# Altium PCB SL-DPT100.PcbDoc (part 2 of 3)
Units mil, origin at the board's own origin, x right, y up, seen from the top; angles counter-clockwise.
Board outline 2881.89 x 2169.29 mil, 4 copper layers (Top Layer, VCC, GND, Bottom Layer); 176 components, 168 nets, 589 pads, 369 vias.
Unrouted connection lines stored in the file: 2.
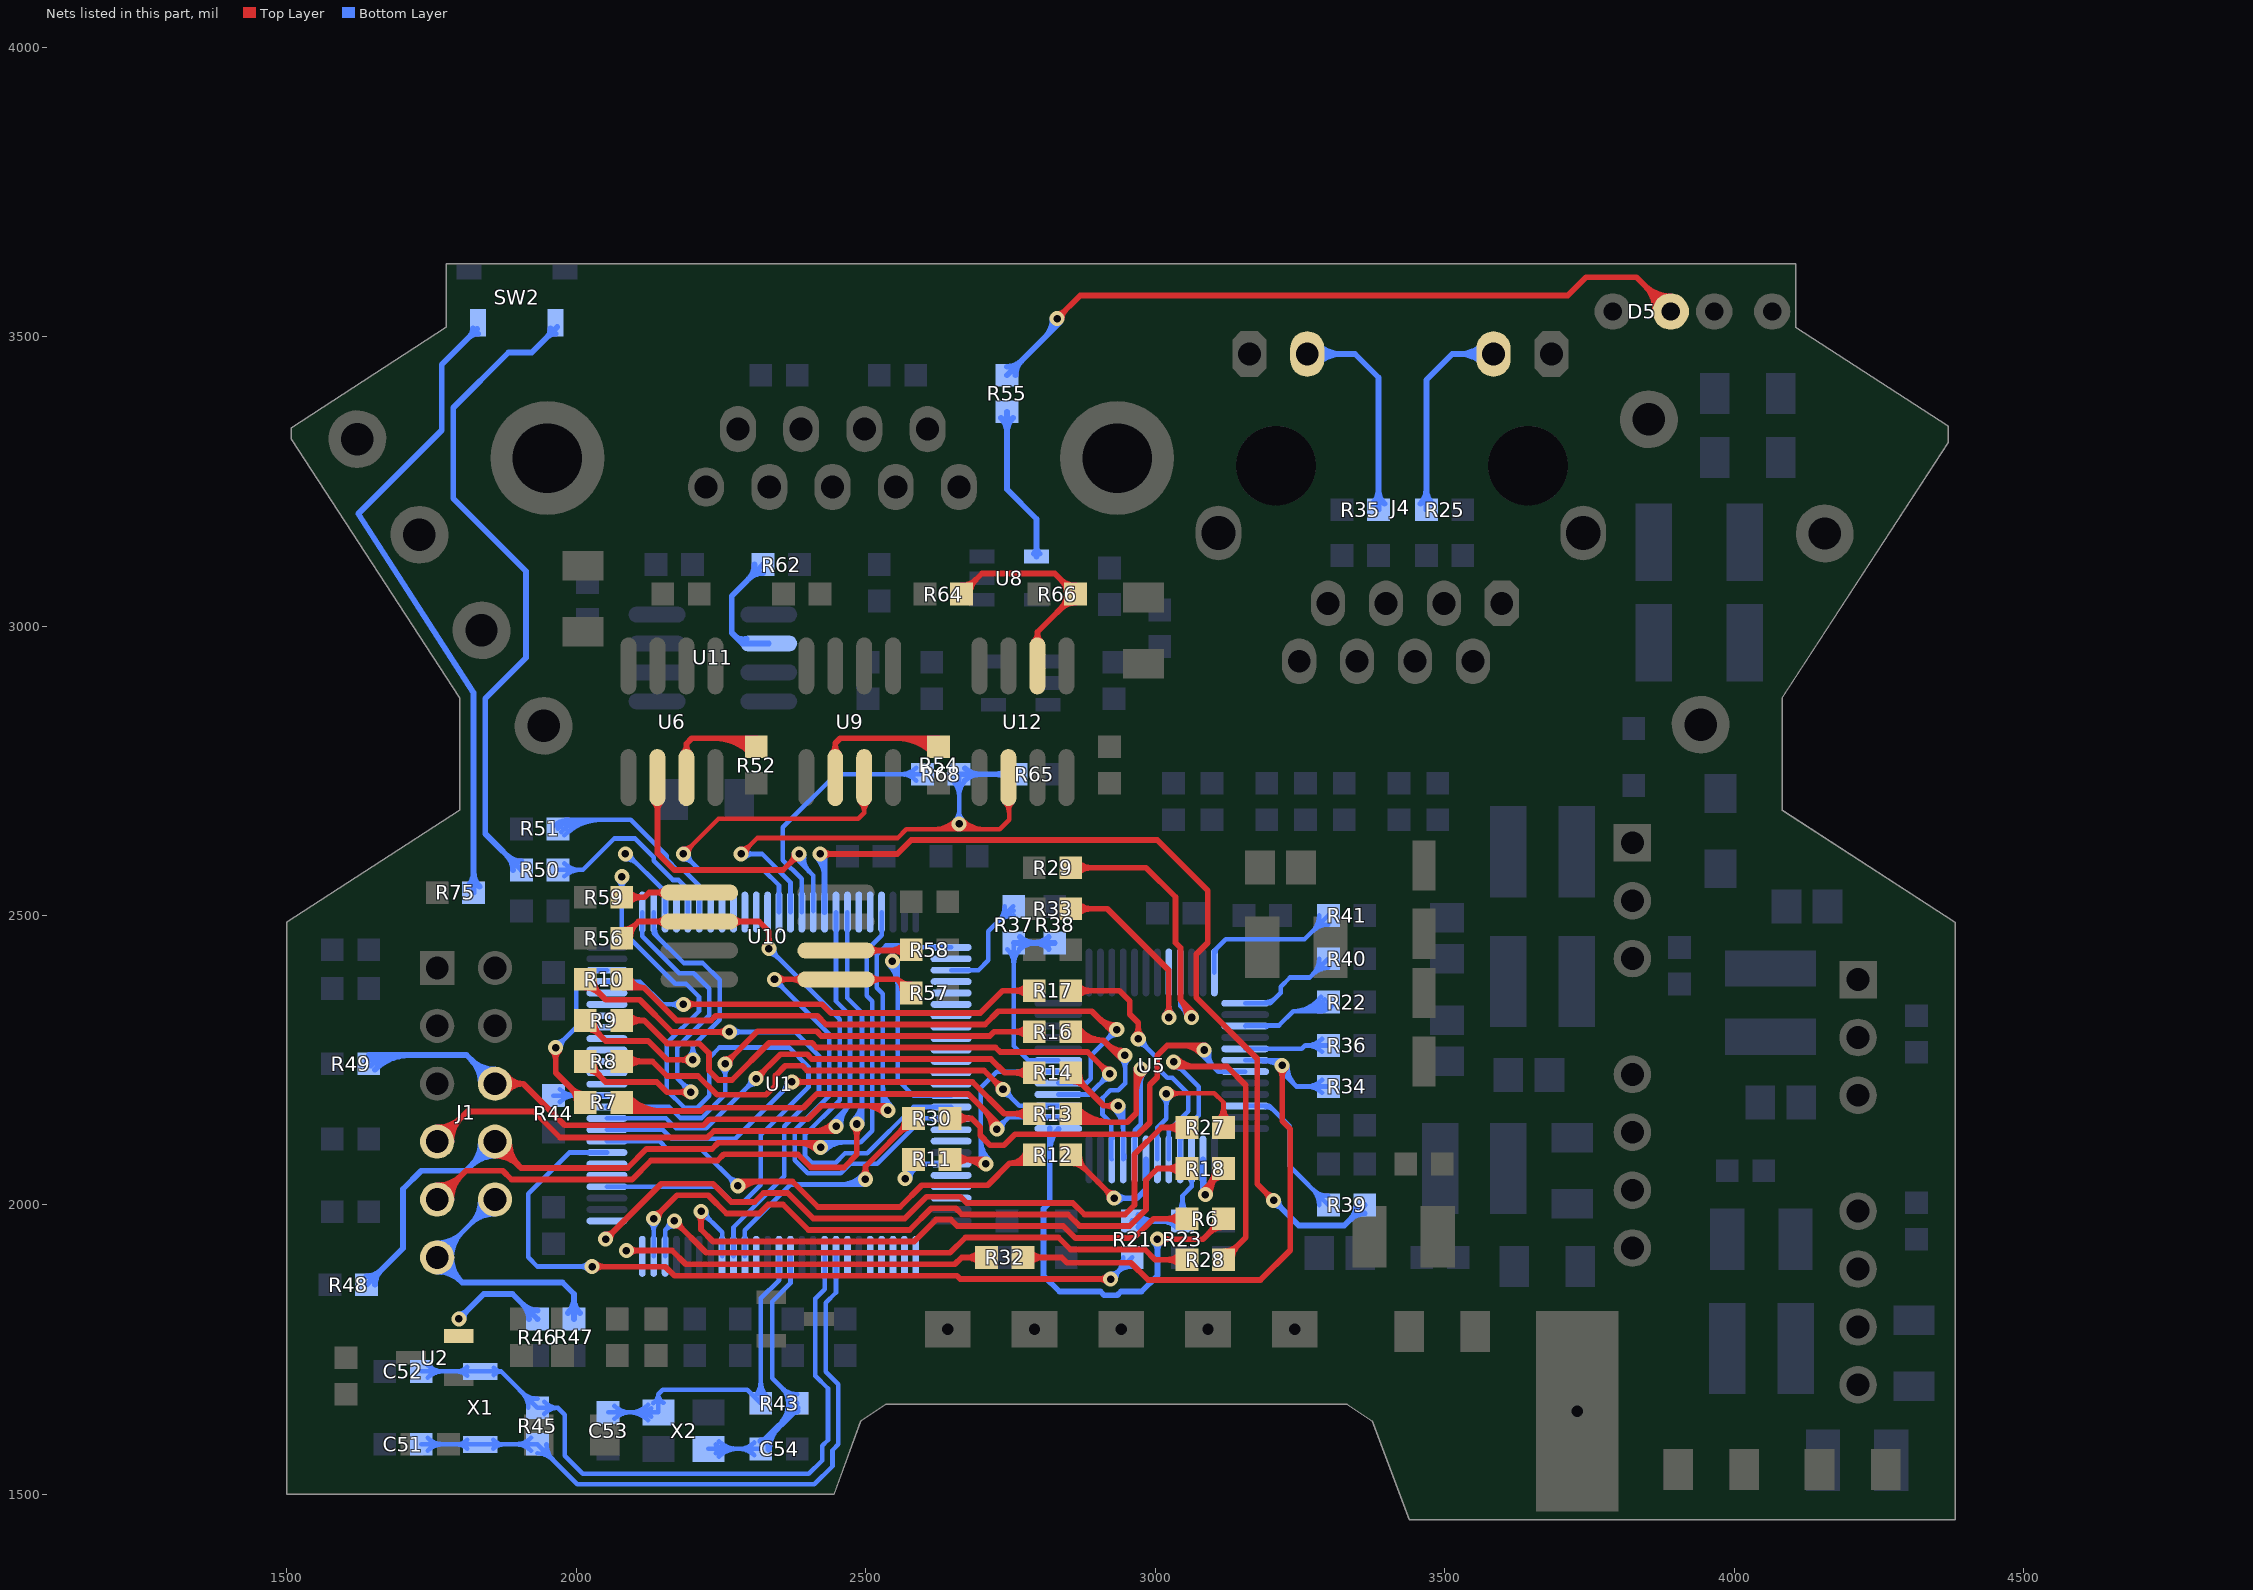
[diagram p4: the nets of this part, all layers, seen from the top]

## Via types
v1: diameter 26, hole 13, Top Layer to Bottom Layer, tented both sides, 363 vias
v2: diameter 26, hole 13, Top Layer to Bottom Layer, 4 vias
v3: diameter 27.56, hole 27.56, Top Layer to Bottom Layer, tented both sides, 2 vias

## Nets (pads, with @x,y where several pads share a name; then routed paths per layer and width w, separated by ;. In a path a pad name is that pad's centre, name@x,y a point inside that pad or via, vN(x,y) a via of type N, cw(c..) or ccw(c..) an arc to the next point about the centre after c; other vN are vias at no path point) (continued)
NetD5_2: D5.2 R55.2 | length 1547.6
  Top Layer w10: v1(2830.71,3531.02) 2870.55,3570.87 3712.6,3570.87 3744.09,3602.36 3831.5,3602.36 D5.2@3890.55,3543.31 ; v1@2830.71,3539.02 ccw(c2830.71,3558.34) 2844.37,3544.68 ccw(c2858.02,3531.02) v1@2838.71,3531.02 ; D5.2@3864.06,3543.31 ccw(c3800.09,3543.31) 3845.32,3588.54 ccw(c3890.55,3633.77) D5.2@3890.55,3569.8 ; D5.2@3874.06,3543.31 ccw(c3834.23,3543.31) 3862.39,3571.47 ccw(c3890.55,3599.63) D5.2@3890.55,3559.8
  Bottom Layer w10: R55.2@2744.09,3433.07 v1@2836.26,3525.24 ; R55.2@2744.09,3447.76 ccw(c2744.09,3483.21) 2769.16,3458.14 ccw(c2794.23,3433.07) R55.2@2758.78,3433.07 ; 2809.03,3498.01 ccw(c2776.02,3531.02) v1@2822.71,3531.02 ; 2826.11,3515.08 ccw(c2810.16,3531.02) v1@2832.71,3531.02
NetJ1_10: J1.10 J1.11 R47.1 | length 975.2
  Bottom Layer w8: J1.11@1759.84,1909.45 J1.10@1858.27,2007.87 ; J1.11@1759.84,1926.98 ccw(c1759.84,1969.29) 1789.76,1939.37 ccw(c1819.69,1909.45) J1.11@1777.37,1909.45 ; J1.11@1759.84,1934.98 ccw(c1759.84,1996.61) 1803.42,1953.03 ccw(c1847,1909.45) J1.11@1785.37,1909.45 ; J1.10@1834.32,2009.45 cw(c1772.69,2009.45) 1816.26,1965.87 cw(c1859.84,1922.29) J1.10@1859.84,1983.92 ; J1.10@1842.32,2009.45 cw(c1800,2009.45) 1829.92,1979.53 cw(c1859.84,1949.61) J1.10@1859.84,1991.92
  Bottom Layer w10: J1.11@1759.84,1884.92 cw(c1759.84,1825.71) 1801.71,1867.58 cw(c1843.58,1909.45) J1.11@1784.37,1909.45 ; J1.11@1759.84,1894.92 cw(c1759.84,1859.85) 1784.64,1884.65 cw(c1809.44,1909.45) J1.11@1774.37,1909.45 ; J1.11@1759.84,1909.45 1803.15,1866.14 1976.38,1866.14 1996.06,1846.46 R47.1@1996.06,1803.15 ; R47.1@1985.68,1813.53 ccw(c1960.61,1838.6) 1996.06,1838.6 ccw(c2031.52,1838.6) R47.1@2006.45,1813.53
NetJ4_10: J4.10 R25.1 | length 562.7
  Bottom Layer w10: R25.1@3458.12,3211.17 ccw(c3433.05,3236.24) 3468.5,3236.24 ccw(c3503.96,3236.24) R25.1@3478.89,3211.17 ; R25.1@3468.5,3200.79 3468.5,3425.2 3513.19,3469.88 J4.10@3584.46,3469.88 ; J4.10@3567.11,3452.53 ccw(c3525.24,3410.66) 3525.24,3469.88 ccw(c3525.24,3529.09) J4.10@3567.11,3487.22 ; J4.10@3574.19,3459.61 ccw(c3549.39,3434.81) 3549.39,3469.88 ccw(c3549.39,3504.95) J4.10@3574.19,3480.15
NetJ4_11: J4.11 R35.1 | length 572
  Bottom Layer w10: J4.11@3262.81,3469.88 3345.08,3469.88 3385.83,3429.13 R35.1@3385.83,3200.79 ; J4.11@3273.08,3459.61 cw(c3297.88,3434.81) 3297.88,3469.88 cw(c3297.88,3504.95) J4.11@3273.08,3480.15 ; J4.11@3280.15,3452.53 cw(c3322.02,3410.66) 3322.02,3469.88 cw(c3322.02,3529.09) J4.11@3280.15,3487.22 ; R35.1@3375.44,3211.17 ccw(c3350.37,3236.24) 3385.83,3236.24 ccw(c3421.28,3236.24) R35.1@3396.21,3211.17
NetR6_1: R6.1 U5.1 | length 833.5
  Top Layer w10: v1(3003.94,1940.94) 3082.68,1940.94 R6.1@3118.11,1976.38 ; v1@3009.59,1935.29 cw(c3023.25,1921.63) 3023.25,1940.94 cw(c3023.25,1960.26) v1@3009.59,1946.6 ; R6.1@3103.43,1976.38 cw(c3067.97,1976.38) 3093.04,1951.31 cw(c3118.11,1926.24) R6.1@3118.11,1961.69
  Bottom Layer w10: 2817.91,2094.06 cw(c2870.51,2094.06) U5.1@2833.32,2131.25 ; U5.1@2817.91,2132.63 2817.91,2004.26 2807.09,1993.43 2807.09,1877.95 2834.65,1850.39 2905.51,1850.39 2911.7,1844.2 2934.76,1844.2 2940.95,1850.39 2976.38,1850.39 3003.94,1877.95 v1(3003.94,1940.94) ; v1@2998.28,1935.29 cw(c2984.62,1921.63) 3003.94,1921.63 cw(c3023.25,1921.63) v1@3009.59,1935.29
NetR7_1: R7.1 U5.2 | length 1038.9
  Top Layer w10: R7.1@2074.98,2173.41 ccw(c2102.03,2200.45) 2102.03,2162.2 ; R7.1@2079.13,2162.6 2079.53,2162.2 2216.14,2162.2 2222.07,2168.13 2392.04,2168.13 2415.84,2191.93 2676.89,2191.93 v1@2732.36,2136.46 ; R7.1@2082.05,2180.48 ccw(c2126.17,2224.59) 2126.17,2162.2 ; R7.1@2089.12,2187.55 ccw(c2150.31,2248.74) 2150.31,2162.2 ; 2704.87,2163.95 cw(c2671.92,2131.01) v1@2718.51,2131.01 ; 2721.94,2146.88 cw(c2706.06,2131.01) v1@2728.51,2131.01
  Bottom Layer w8: v1@2726.38,2130.91 2747.32,2151.85 U5.2@2832.52,2151.85 ; v1@2726.51,2140.01 ccw(c2726.51,2161.67) 2741.83,2146.35 ; v1@2735.51,2131.01 cw(c2757.31,2131.01) 2741.9,2146.42
  other v1: 2726.51,2131.01
NetR8_1: R8.1 U5.3 | length 957.6
  Top Layer w10: R8.1@2078.74,2248.03 2131.64,2248.03 2156.84,2222.83 2210.52,2222.83 2243.08,2190.27 2328.06,2190.27 2344.09,2206.3 2344.09,2223.43 2361.11,2240.44 2390.77,2240.44 2398.8,2232.4 2704.61,2232.4 v1(2737.2,2199.8) ; R8.1@2089.12,2237.65 cw(c2114.19,2212.58) 2114.19,2248.03 cw(c2114.19,2283.48) R8.1@2089.12,2258.42 ; v1@2729.2,2199.8 ccw(c2709.89,2199.8) 2723.55,2213.46 ccw(c2737.2,2227.12) v1@2737.2,2207.8
  Bottom Layer w8: v1@2737.05,2200.08 2737.05,2199.96 2765.47,2171.54 U5.3@2832.52,2171.54 ; v1@2737.2,2190.8 cw(c2737.2,2169.08) 2752.57,2184.44 cw(c2767.93,2199.8) v1@2746.2,2199.8
NetR9_1: R9.1 U5.4 | length 1176
  Top Layer w10: R9.1@2078.74,2318.9 2117.11,2318.9 2157.07,2278.93 2212.61,2278.93 2229.24,2262.3 2229.24,2232.17 2245.55,2215.86 2269,2215.86 2333.27,2280.13 2407.2,2280.13 2415.24,2272.09 2724.48,2272.09 2732.31,2264.25 2883.39,2264.25 v1(2921.26,2226.38) ; R9.1@2089.12,2308.51 cw(c2114.19,2283.44) 2114.19,2318.9 cw(c2114.19,2354.35) R9.1@2089.12,2329.28 ; v1@2913.26,2226.38 ccw(c2893.95,2226.38) 2907.6,2240.04 ccw(c2921.26,2253.69) v1@2921.26,2234.38
  Bottom Layer w8: U5.4@2832.68,2190.94 2886.45,2190.94 v1@2922.07,2226.56 ; 2905.45,2209.94 ccw(c2889.02,2226.38) v1@2912.26,2226.38 ; 2906.97,2211.46 cw(c2921.26,2197.16) v1@2921.26,2217.38
NetR10_1: R10.1 U5.5 | length 1215.9
  Top Layer w10: R10.1@2081.61,2375.08 2117.05,2375.08 ; R10.1@2083.26,2390.98 ccw(c2104,2396.55) 2104,2375.08 ; R10.1@2092.92,2393.58 ccw(c2117.05,2400.06) 2117.05,2375.08 ; 2900.85,2324.35 ccw(c2933.66,2357.16) v1@2933.66,2310.76 ; 2917.92,2307.28 ccw(c2933.66,2323.02) v1@2933.66,2300.76 ; v1@2928.35,2296.85 2890.55,2334.65 2728.85,2334.65 2705.97,2311.77 2431.68,2311.77 2416.71,2326.74 2240.91,2326.74 2232.79,2318.61 2173.51,2318.61 2117.05,2375.08
  Bottom Layer w8: U5.5@2832.68,2210.63 2880.91,2210.63 2888.65,2218.37 2888.65,2257.54 v1@2933.86,2302.76 ; 2918.16,2287.06 ccw(c2902.46,2302.76) v1@2924.66,2302.76 ; 2918.63,2287.53 cw(c2933.66,2272.5) v1@2933.66,2293.76
  other v1: 2933.66,2302.76
NetR11_1: R11.1 U5.6 | length 516.9
  Top Layer w10: R11.1@2645.67,2078.74 v1@2708.66,2078.74 ; R11.1@2656.05,2068.36 cw(c2681.12,2043.29) 2681.12,2078.74 cw(c2681.12,2114.19) R11.1@2656.05,2089.12 ; 2669.35,2078.74 cw(c2669.35,2032.54) v1@2702.02,2065.21 ; 2693.5,2078.74 cw(c2693.5,2056.69) v1@2709.09,2072.28
  Bottom Layer w8: v1@2698.82,2069.88 2698.82,2202.76 2726.38,2230.32 U5.6@2832.68,2230.32 ; 2698.82,2094.67 ccw(c2731.48,2094.67) v1@2708.38,2071.57 ; 2698.82,2113.98 ccw(c2750.79,2113.98) v1@2714.04,2077.23
  other v1: 2707.68,2070.87
NetR12_1: R12.1 U5.43 | length 390.7
  Top Layer w10: R12.1@2854.33,2086.61 2901.29,2039.65 v1(2929.13,2011.81) ; 2915.47,2025.48 cw(c2901.81,2011.81) v1@2921.13,2011.81 ; 2915.49,2025.46 ccw(c2929.13,2039.11) v1@2929.13,2019.81 ; 2879.4,2061.55 cw(c2904.47,2086.61) 2869.02,2086.61 ccw(c2904.47,2086.61) 2879.4,2061.55 ; 2879.4,2061.55 ccw(c2854.33,2036.48) 2854.33,2071.93 cw(c2854.33,2036.48) 2879.4,2061.55
  Bottom Layer w10: v1(2929.13,2011.81) 2968.5,2011.81 2984.25,2027.56 U5.43@2984.25,2078.74 ; v1@2934.79,2006.15 cw(c2948.45,1992.5) 2948.45,2011.81 cw(c2948.45,2031.12) v1@2934.79,2017.47
NetR13_1: R13.1 U5.44 | length 594.2
  Top Layer w10: R13.1@2850.57,2153.72 ccw(c2876.95,2180.1) 2876.95,2142.79 ; R13.1@2854.34,2142.85 2854.4,2142.79 2951.89,2142.79 2967.4,2158.31 v1@2967.4,2235.94 ; R13.1@2857.64,2160.79 ccw(c2901.1,2204.25) 2901.1,2142.79 ; R13.1@2864.71,2167.86 ccw(c2925.24,2228.39) 2925.24,2142.79 ; 2967.4,2196.63 cw(c3014,2196.63) v1@2981.05,2229.58 ; 2967.4,2220.77 cw(c2989.86,2220.77) v1@2973.98,2236.65
  Bottom Layer w8: U5.44@2964.57,2078.74 2964.69,2078.87 2964.69,2129.06 2975.39,2139.76 v1@2975.39,2238.19 ; v1@2969.03,2228.87 cw(c2953.67,2213.51) 2975.39,2213.51 cw(c2997.12,2213.51) v1@2981.76,2228.87
  other v1: 2975.39,2235.24
NetR14_1: R14.1 U5.45 | length 382
  Top Layer w10: R14.1@2854.33,2213.66 cw(c2854.33,2178.21) 2879.4,2203.28 cw(c2904.47,2228.35) R14.1@2869.02,2228.35 ; R14.1@2854.33,2228.35 2911.42,2171.26 v1(2936.02,2171.26) ; v1@2930.37,2165.6 ccw(c2916.71,2151.95) 2916.71,2171.26 ccw(c2916.71,2190.57) v1@2930.37,2176.92
  Bottom Layer w8: v1@2929.66,2164.9 cw(c2892.91,2128.15) 2944.88,2128.15 ; v1@2935.32,2170.55 cw(c2912.22,2147.46) 2944.88,2147.46 ; U5.45@2944.88,2101.2 U5.45@2944.88,2078.74 ; v1@2944.88,2172.24 U5.45@2944.88,2078.74 ; U5.45@2946.79,2086.19 2946.72,2086.13 2946.72,2080.58 U5.45@2944.88,2078.74
NetR16_1: R16.1 U5.46 | length 517.3
  Top Layer w10: R16.1@2849.96,2296.19 ccw(c2872.18,2311.53) R16.1@2872.18,2284.53 ; R16.1@2858.19,2301.87 ccw(c2891.23,2324.67) 2891.23,2284.53 ; R16.1@2858.39,2284.53 2910.28,2284.53 v1@2942.36,2252.44 ; R16.1@2866.42,2307.55 ccw(c2910.27,2337.81) 2910.27,2284.53 ; 2915.93,2278.88 ccw(c2946.41,2309.36) v1@2947.61,2266.26 ; 2932.35,2262.45 ccw(c2947.3,2277.41) v1@2947.89,2256.27
  Bottom Layer w8: 2924.12,2121.38 ccw(c2932.4,2121.38) U5.46@2926.54,2115.52 ; U5.46@2925.2,2078.74 2924.12,2079.82 2924.12,2141.07 2909.18,2156.01 2909.18,2184.77 2922.51,2198.1 2936.29,2198.1 2948.1,2209.91 v1@2948.1,2258.59 ; v1@2941.47,2251.9 cw(c2925.46,2235.89) 2948.1,2235.89 ; 2948.1,2237.19 cw(c2968.92,2237.19) v1@2954.2,2251.9
  other v1: 2947.83,2258.27
NetR17_1: R17.1 U5.41 | length 563.7
  Top Layer w10: R17.1@2854.33,2370.08 2897.64,2370.08 2938.58,2370.08 2956.24,2352.43 2956.24,2329.47 2970.87,2314.84 v1@2970.87,2287.01 ; R17.1@2864.71,2359.7 cw(c2889.78,2334.63) 2889.78,2370.08 cw(c2889.78,2405.53) R17.1@2864.71,2380.46 ; v1@2965.21,2292.47 ccw(c2951.55,2306.13) 2970.87,2306.13 ccw(c2990.18,2306.13) v1@2976.52,2292.47
  Bottom Layer w8: v1@2970.87,2277.81 cw(c2970.87,2256.56) 2985.89,2271.59 ; v1@2970.87,2286.61 3002.24,2255.24 3002.24,2238.71 3021.09,2219.86 3029.91,2219.86 3057.35,2192.41 3057.35,2162.04 3023.62,2128.31 U5.41@3023.62,2078.74 ; v1@2979.87,2286.81 ccw(c3002.07,2286.81) 2986.37,2271.11
  other v1: 2970.87,2286.81
NetR18_1: R18.1 U5.38 | length 288.5
  Top Layer w8: v1@3078.74,2021.65 R18.1@3118.11,2061.02 ; v1@3087.76,2017.82 cw(c3118.82,2017.82) 3096.86,2039.77 ; 3089.94,2032.86 ccw(c3059.81,2062.99) R18.1@3102.43,2062.99 ; 3094.69,2037.61 cw(c3118.11,2014.19) R18.1@3118.11,2047.31 ; v1@3095.76,2017.82 cw(c3146.13,2017.82) R18.1@3110.52,2053.43 ; R18.1@3103.6,2046.51 ccw(c3087.12,2062.99) R18.1@3110.43,2062.99
  Bottom Layer w10: v1@3082.68,2013.78 U5.38@3082.68,2078.74 ; U5.38@3082.68,2047 ccw(c3115.95,2047) v1@3092.42,2023.47
  other v1: 3086.76,2017.82
NetR21_1: R21.1 R23.1 U5.39 | length 392.6
  Bottom Layer w8: R23.1@3036.15,1983.53 ccw(c3009.38,2010.31) 3047.24,2010.31 ccw(c3085.11,2010.31) R23.1@3058.34,1983.53 ; R23.1@3047.24,1972.44 3062.99,1972.44 3047.24,1988.19 3047.24,2016.26 3062.99,2032 U5.39@3062.99,2078.74
  Bottom Layer w10: R21.1@2960.63,1972.44 R23.1@3047.24,1972.44 ; R21.1@2971.01,1962.06 cw(c2996.08,1936.99) 2996.08,1972.44 cw(c2996.08,2007.89) R21.1@2971.01,1982.82 ; R23.1@3036.86,1962.06 ccw(c3011.79,1936.99) 3011.79,1972.44 ccw(c3011.79,2007.89) R23.1@3036.86,1982.82
NetR22_2: R22.2 U5.27 | length 310.8
  Bottom Layer w8: U5.27@3155.51,2309.06 3156.59,2310.13 3213.91,2310.13 3238.42,2334.65 ; U5.27@3192.29,2307.71 cw(c3198.15,2301.85) 3198.15,2310.13 ; 3253.89,2334.65 ccw(c3253.89,2382.5) R22.2@3292.94,2354.84 ; 3269.36,2334.65 ccw(c3269.36,2371.54) R22.2@3299.47,2350.21 ; R22.2@3284.84,2334.65 ccw(c3284.84,2360.58) R22.2@3306,2345.59 ; R22.2@3286.41,2359.46 cw(c3238.42,2393.46) 3238.42,2334.65 ; R22.2@3287.4,2334.65 3238.42,2334.65
NetR27_1: R27.1 U5.42 | length 396.1
  Top Layer w8: v1@3019.68,2192.91 3102.36,2192.91 3118.11,2177.17 R27.1@3118.11,2133.86 ; v1@3025.65,2186.15 cw(c3041.97,2169.83) 3041.97,2192.91 ; v1@3025.65,2198.88 ccw(c3040.05,2213.28) 3040.05,2192.91 ; R27.1@3107.02,2144.95 ccw(c3080.24,2171.73) 3118.11,2171.73 ccw(c3155.98,2171.73) R27.1@3129.2,2144.95
  Bottom Layer w8: U5.42@3003.94,2078.74 3003.94,2133.86 3019.29,2149.21 v1(3019.29,2192.52) ; v1@3012.92,2186.15 cw(c2997.56,2170.79) 3019.29,2170.79 cw(c3041.01,2170.79) v1@3025.65,2186.15
NetR28_1: R28.1 U5.40 | length 819.4
  Top Layer w10: v1@3030.43,2239.25 3123.94,2239.25 3156.5,2206.69 3156.5,1943.9 R28.1@3118.11,1905.51 ; v1@3030.59,2245.63 ccw(c3046,2261.04) 3046,2239.25 ; v1@3037.66,2252.7 ccw(c3070.14,2285.18) 3070.14,2239.25 ; R28.1@3118.11,1920.2 ccw(c3118.11,1955.65) 3143.18,1930.58 ccw(c3168.25,1905.51) R28.1@3132.8,1905.51
  Bottom Layer w8: v1@3032.01,2238.05 cw(c3032.01,2215.18) 3048.18,2231.35 ; v1@3031.99,2247.54 3075.2,2204.33 3075.2,2154.65 3043.31,2122.76 U5.40@3043.31,2078.74 ; v1@3041.01,2247.05 ccw(c3061.6,2247.05) 3047.04,2232.49 ; U5.40@3045.21,2114.17 cw(c3070.55,2114.17) 3052.63,2132.09
  other v1: 3032.01,2247.05
NetR29_2: R29.2 U5.21 | length 665.7
  Top Layer w10: R29.2@2854.33,2582.68 2984.25,2582.68 3035.15,2531.78 3035.15,2453.03 3043.7,2444.48 3043.7,2354.33 v1@3069.29,2328.74 ; R29.2@2864.71,2572.29 cw(c2889.78,2547.22) 2889.78,2582.68 cw(c2889.78,2618.13) R29.2@2864.71,2593.06 ; 3044.14,2353.64 cw(c3008.63,2323.83) v1@3054.99,2323.83 ; 3058.48,2339.55 cw(c3042.77,2323.83) v1@3064.99,2323.83 ; 3058.57,2339.46 cw(c3043.06,2323.96) v1@3064.99,2323.82
  Bottom Layer w8: U5.21@3043.31,2405.51 3043.31,2343.69 v1@3062.99,2324.01 ; v1@3053.99,2323.83 ccw(c3032.26,2323.83) 3047.63,2339.2 ccw(c3062.99,2354.56) v1@3062.99,2332.83
  other v1: 3062.99,2323.83
NetR30_1: R30.1 U5.31 | length 853.6
  Top Layer w10: R30.1@2646.65,2149.61 2683.07,2149.61 2697.83,2134.84 2697.83,2120.31 2714.98,2103.17 2738.99,2103.17 2757.87,2122.05 2970.52,2122.05 2990.55,2142.08 2990.55,2207.49 3003.54,2220.48 3003.54,2258.27 3020.87,2275.59 v1@3086.61,2275.59 ; R30.1@2656.05,2139.22 cw(c2681.12,2114.15) 2681.12,2149.61 cw(c2681.12,2185.06) R30.1@2656.05,2159.99 ; 3046.24,2275.59 cw(c3046.24,2229.39) v1@3078.91,2262.06 ; 3070.39,2275.59 cw(c3070.39,2253.54) v1@3085.98,2269.13
  Bottom Layer w8: v1@3077.76,2261.81 3109.25,2230.32 U5.31@3155.51,2230.32 ; v1@3085.55,2267.55 ccw(c3108.04,2263.77) 3091.92,2247.65 ; v1@3093.44,2266.23 ccw(c3126.84,2260.62) 3102.89,2236.67
  other v1: 3084.57,2267.72
NetR32_1: R32.1 R34.1 U5.30 | length 1256.4
  Top Layer w10: R32.1@2771.65,1909.45 2838.58,1909.45 2847.72,1900.32 2957.95,1900.32 2988.03,1870.24 3181.76,1870.24 3233.27,1921.74 3233.27,2131.38 3219.49,2145.16 v1(3219.49,2241.14) ; R32.1@2782.04,1899.06 cw(c2807.11,1874) 2807.11,1909.45 cw(c2807.11,1944.9) R32.1@2782.04,1919.83 ; v1@3213.83,2235.48 cw(c3200.17,2221.83) 3219.49,2221.83 cw(c3238.8,2221.83) v1@3225.15,2235.48
  Bottom Layer w8: U5.30@3155.51,2250 v1@3218.5,2250 ; U5.30@3186.4,2248.6 cw(c3186.4,2196.24) v1@3223.43,2233.27 ; U5.30@3195.69,2250 cw(c3195.69,2217.34) v1@3218.78,2240.43 ; v1@3215.55,2233.27 3244.09,2204.72 R34.1@3299.21,2204.72 ; v1@3220.49,2241.12 ccw(c3249.46,2240.34) 3228.97,2219.85 ; v1@3228.49,2240.9 ccw(c3275.09,2239.66) 3242.12,2206.69 ; R34.1@3288.12,2193.63 ccw(c3261.35,2166.86) 3261.35,2204.72 ccw(c3261.35,2242.59) R34.1@3288.12,2215.82
NetR33_2: R33.2 U5.20 | length 494.9
  Top Layer w10: R33.2@2854.33,2511.81 2917.32,2511.81 3023.62,2405.51 v1(3023.62,2323.83) v1@3023.62,2322.83 ; R33.2@2864.71,2501.43 cw(c2889.78,2476.36) 2889.78,2511.81 cw(c2889.78,2547.26) R33.2@2864.71,2522.19 ; v1@3017.97,2329.49 ccw(c3004.31,2343.15) 3023.62,2343.15 ccw(c3042.94,2343.15) v1@3029.28,2329.49
  Bottom Layer w8: v1@3017.26,2330.2 ccw(c3001.89,2345.56) 3023.62,2345.56 ccw(c3045.35,2345.56) v1@3029.99,2330.2 ; v1@3023.62,2322.83 U5.20@3023.62,2401.57
NetR36_1: R36.1 U5.29 | length 205.6
  Bottom Layer w8: U5.29@3155.51,2269.68 3253.51,2269.68 3259.42,2275.59 R36.1@3299.21,2275.59 ; R36.1@3288.12,2264.5 ccw(c3261.35,2237.72) 3261.35,2275.59 ccw(c3261.35,2313.46) R36.1@3288.12,2286.68
NetR37_1: R37.1 R38.1 U5.7 | length 506.8
  Bottom Layer w8: R37.1@2744.81,2441.67 cw(c2718.04,2414.89) 2755.91,2414.89 cw(c2793.77,2414.89) R37.1@2767,2441.67 ; R37.1@2755.91,2452.76 2755.91,2274.61 2780.51,2250 U5.7@2832.68,2250
  Bottom Layer w10: R37.1@2755.91,2452.76 R38.1@2826.77,2452.76 ; R37.1@2766.29,2442.37 cw(c2791.36,2417.3) 2791.36,2452.76 cw(c2791.36,2488.21) R37.1@2766.29,2463.14 ; R38.1@2816.39,2442.37 ccw(c2791.32,2417.3) 2791.32,2452.76 ccw(c2791.32,2488.21) R38.1@2816.39,2463.14
NetR39_1: R39.1 U5.34 | length 330.1
  Bottom Layer w8: U5.34@3155.51,2171.26 3197.17,2171.26 3232.28,2136.14 3232.28,2066.93 R39.1@3299.21,2000 ; U5.34@3190.95,2169.35 cw(c3190.95,2149.74) 3204.82,2163.61 ; R39.1@3283.53,2000 ccw(c3245.66,2000) 3272.44,2026.78 ccw(c3299.21,2053.55) R39.1@3299.21,2015.69
NetR40_1: R40.1 U5.25 | length 259.9
  Bottom Layer w8: U5.25@3155.51,2348.43 3198.82,2348.43 3215.57,2365.18 ; U5.25@3190.95,2350.33 ccw(c3190.95,2373.94) 3207.64,2357.25 ; 3215.57,2365.23 3216.49,2366.14 3216.9,2366.14 3216.9,2371.72 3217.25,2372.07 3217.25,2377.26 3232.98,2392.98 3267,2392.98 R40.1@3299.21,2425.2 ; R40.1@3283.53,2425.2 cw(c3245.66,2425.2) 3272.44,2398.42 cw(c3299.21,2371.64) R40.1@3299.21,2409.51
NetR41_1: R41.1 U5.24 | length 327.2
  Bottom Layer w8: U5.24@3102.36,2401.57 3102.36,2439.33 3121.82,2458.79 3258,2458.79 R41.1@3299.21,2500 ; U5.24@3104.27,2437.01 cw(c3114.48,2437.01) 3107.26,2444.23 ; R41.1@3283.53,2500 cw(c3245.66,2500) 3272.44,2473.22 cw(c3299.21,2446.45) R41.1@3299.21,2484.32
NetR46_2: R46.2 U2.2 | length 257.5
  Bottom Layer w10: v1(1797.24,1803.15) 1840.3,1846.2 1890.02,1846.2 R46.2@1933.07,1803.15 ; v1@1797.24,1811.15 ccw(c1797.24,1830.46) 1810.9,1816.81 ccw(c1824.56,1803.15) v1@1805.24,1803.15 ; R46.2@1918.39,1803.15 ccw(c1882.93,1803.15) 1908,1828.22 ccw(c1933.07,1853.29) R46.2@1933.07,1817.83
NetR50_2: R50.2 SW2.1 | length 1231.8
  Bottom Layer w10: R50.2@1890.83,2578.74 ccw(c1855.37,2578.74) 1880.44,2603.81 ccw(c1905.51,2628.88) R50.2@1905.51,2593.43 ; R50.2@1905.51,2578.74 1842.91,2641.34 1842.91,2874.91 1913.39,2945.38 1913.39,3094.49 1787.56,3220.32 1787.56,3377.13 1882.87,3472.44 1923.23,3472.44 SW2.1@1967.13,3516.34 ; SW2.1@1955.79,3513.78 cw(c1934.59,3513.78) 1949.58,3498.79 cw(c1964.57,3483.8) SW2.1@1964.57,3505
NetR52_2: R52.2 U6.3 | length 361
  Top Layer w10: U6.3@2184.15,2779.83 ccw(c2169.16,2794.82) 2190.35,2794.82 ccw(c2211.55,2794.82) U6.3@2196.56,2779.83 ; U6.3@2190.35,2738.19 2190.35,2796.65 2199.72,2806.02 R52.2@2310.95,2806.02 ; 2240.12,2806.02 cw(c2240.12,2720.43) R52.2@2300.64,2780.95 ; 2264.26,2806.02 cw(c2264.26,2744.57) R52.2@2307.71,2788.03 ; 2288.4,2806.02 cw(c2288.4,2768.72) R52.2@2314.78,2795.1
NetR54_2: R54.2 U9.2 | length 417.1
  Top Layer w10: U9.2@2441.43,2780.03 ccw(c2428.42,2793.9) 2447.44,2793.9 ccw(c2466.46,2793.9) U9.2@2453.45,2780.03 ; U9.2@2447.44,2738.19 2447.44,2797.44 2456.02,2806.02 R54.2@2625.91,2806.02 ; 2555.08,2806.02 cw(c2555.08,2720.43) R54.2@2615.6,2780.95 ; 2579.22,2806.02 cw(c2579.22,2744.58) R54.2@2622.67,2788.03 ; 2603.36,2806.02 cw(c2603.36,2768.72) R54.2@2629.74,2795.1
NetR55_1: R55.1 U8.4 | length 352.7
  Bottom Layer w10: R55.1@2733.71,3359.69 cw(c2708.64,3334.63) 2744.09,3334.63 cw(c2779.55,3334.63) R55.1@2754.48,3359.69 ; R55.1@2744.09,3370.08 2744.09,3236.22 2795.28,3185.04 U8.4@2795.28,3120.08 ; U8.4@2790.46,3124.89 ccw(c2778.83,3136.52) 2795.28,3136.52 ccw(c2811.72,3136.52) U8.4@2800.09,3124.89
NetR64_1: R64.1 R66.2 U12.2 | length 585.6
  Top Layer w10: R64.1@2665.35,3055.12 2700.79,3090.55 2826.77,3090.55 R66.2@2862.2,3055.12 2796.65,2989.57 U12.2@2796.65,2923.23 ; R64.1@2665.35,3069.8 ccw(c2665.35,3105.26) 2690.42,3080.19 ccw(c2715.49,3055.12) R64.1@2680.04,3055.12 ; U12.2@2790.45,2972.74 ccw(c2775.46,2987.73) 2796.65,2987.73 ccw(c2817.85,2987.73) U12.2@2802.86,2972.74 ; R66.2@2862.2,3040.43 ccw(c2862.2,3004.98) 2837.14,3030.05 ccw(c2812.07,3055.12) 2847.52,3055.12 ccw(c2812.07,3055.12) 2837.14,3080.19 ccw(c2862.2,3105.26) R66.2@2862.2,3069.8
NetR75_1: R75.1 SW2.2 | length 1206.4
  Bottom Layer w10: R75.1@1812.45,2549.75 ccw(c1787.38,2574.82) 1822.83,2574.82 ccw(c1858.29,2574.82) R75.1@1833.22,2549.75 ; 1814.38,3498.24 cw(c1830.71,3481.9) SW2.2@1830.71,3505 ; 1816.28,3500.14 ccw(c1802.63,3513.78) SW2.2@1821.93,3513.78 ; R75.1@1822.83,2539.37 1822.83,2884.65 1623.52,3193.84 1767.72,3338.04 1767.72,3451.57 SW2.2@1829.13,3512.99
OSC_IN: C54.2 R43.1 U1.12 X2.1 | length 793.5
  Bottom Layer w8: X2.1@2228.35,1578.74 C54.2@2318.9,1578.74 ; X2.1@2241.12,1571.15 cw(c2259.45,1552.81) 2259.45,1578.74 ; X2.1@2241.12,1586.19 ccw(c2259.11,1604.18) 2259.11,1578.74 ; X2.1@2246.78,1565.49 cw(c2278.77,1533.5) 2278.77,1578.74 ; X2.1@2246.78,1591.85 ccw(c2278.42,1623.49) 2278.42,1578.74 ; C54.2@2307.81,1567.65 ccw(c2281.03,1540.87) 2281.03,1578.74 ccw(c2281.03,1616.61) C54.2@2307.81,1589.83 ; R43.1@2366.2,1657.48 ccw(c2328.34,1657.48) 2355.11,1684.26 ccw(c2381.89,1711.03) R43.1@2381.89,1673.17 ; U1.12@2370.08,1911.42 2370.08,1864.73 2338.58,1833.24 2338.58,1700.79 R43.1@2381.89,1657.48
  Bottom Layer w11.81: C54.2@2318.9,1592.52 ccw(c2318.9,1606.78) C54.2@2328.98,1596.7 ; C54.2@2322.83,1590.55 R43.1@2381.89,1649.61 ; C54.2@2332.68,1578.74 cw(c2384.95,1578.74) 2347.99,1615.7 ; 2352.8,1620.52 ccw(c2315.83,1657.48) R43.1@2368.11,1657.48 ; R43.1@2371.81,1639.53 cw(c2381.89,1629.44) R43.1@2381.89,1643.7
OSC_OUT: C53.2 R43.2 U1.13 X2.3 | length 842.4
  Bottom Layer w8: C53.2@2055.12,1641.73 2141.73,1641.73 2141.73,1673.23 ; C53.2@2066.21,1630.64 cw(c2092.99,1603.87) 2092.99,1641.73 cw(c2092.99,1679.6) C53.2@2066.21,1652.82 ; 2091.97,1641.73 cw(c2091.97,1596.49) X2.3@2123.96,1628.48 ; 2092.32,1641.73 ccw(c2092.32,1686.48) X2.3@2123.96,1654.84 ; 2111.29,1641.73 cw(c2111.29,1615.81) X2.3@2129.62,1634.14 ; 2111.63,1641.73 ccw(c2111.63,1667.17) X2.3@2129.62,1649.18 ; X2.3@2132.81,1657.84 ccw(c2124,1673.23) 2141.73,1673.23 ; X2.3@2150.81,1658.12 cw(c2158.85,1673.23) 2141.73,1673.23 ; R43.2@2307.81,1668.57 ccw(c2281.03,1695.35) 2318.9,1695.35 ccw(c2356.76,1695.35) R43.2@2329.99,1668.57 ; U1.13@2350.39,1911.42 2350.39,1870.28 2318.9,1838.79 R43.2@2318.9,1657.48 2295.28,1681.1 2149.61,1681.1 2141.73,1673.23
PA0: R28.2 U1.23 | length 1123.5
  Top Layer w10: v1@2169.69,1964.44 cw(c2169.69,1945.13) 2183.34,1958.78 cw(c2197,1972.44) v1@2177.69,1972.44 ; v1(2169.69,1972.44) 2224.8,1917.32 2645.67,1917.32 2672.33,1943.98 2833.08,1943.98 2853.99,1923.07 2982.44,1923.07 2999.99,1905.51 R28.2@3055.12,1905.51 ; R28.2@3044.73,1895.13 ccw(c3019.67,1870.06) 3019.67,1905.51 ccw(c3019.67,1940.96) R28.2@3044.73,1915.9
  Bottom Layer w8: U1.23@2153.54,1911.42 2153.54,1956.69 v1@2169.68,1972.83 ; v1@2160.69,1972.44 cw(c2138.96,1972.44) 2154.32,1957.08 cw(c2169.69,1941.71) v1@2169.69,1963.44
PA1: R18.2 U1.24 | length 1260.2
  Top Layer w10: v1@2133.86,1984.38 ccw(c2133.86,2003.69) 2147.52,1990.03 ccw(c2161.17,1976.38) v1@2141.86,1976.38 ; v1@2134.06,1976.57 2174.3,2016.82 2228.15,2016.82 2259.58,1985.39 2316.2,1985.39 2331.6,2000.79 2357.29,2000.79 2401.07,1957.01 2575.6,1957.01 2613.13,1994.54 2655.58,1994.54 2666.45,1983.66 2849.52,1983.66 2869.6,1963.58 2956.21,1963.58 2984.25,1991.62 2984.25,2043.31 3003.94,2062.99 R18.2@3055.12,2062.99 ; R18.2@3044.73,2052.61 ccw(c3019.67,2027.54) 3019.67,2062.99 ccw(c3019.67,2098.44) R18.2@3044.73,2073.38
  Bottom Layer w8: v1@2127.49,1970.01 cw(c2112.13,1954.65) 2133.86,1954.65 cw(c2155.59,1954.65) v1@2140.22,1970.01 ; U1.24@2133.86,1911.42 v1(2133.86,1976.38)
PA2: R32.2 U1.25 | length 775.1
  Top Layer w10: v1(2086.61,1921.26) 2165.35,1921.26 2189.13,1897.48 2653.89,1897.48 2665.86,1909.45 R32.2@2705.2,1909.45 ; v1@2092.27,1915.6 cw(c2105.93,1901.95) 2105.93,1921.26 cw(c2105.93,1940.57) v1@2092.27,1926.92 ; 2673.21,1909.45 cw(c2673.21,1874) 2698.28,1899.06 ccw(c2673.21,1874) 2673.21,1909.45 ; 2673.21,1909.45 ccw(c2673.21,1944.9) 2698.28,1919.83 cw(c2673.21,1944.9) 2673.21,1909.45
PA3: R27.2 U1.26 | length 1365
  Top Layer w10: v1@2051,1948.94 ccw(c2051,1968.7) 2064.97,1954.73 ; v1@2051.18,1940.94 2146.9,2036.66 2236.37,2036.66 2267.8,2005.23 2307.98,2005.23 2323.58,2020.83 2365.31,2020.83 2409.29,1976.85 2567.38,1976.85 2604.91,2014.38 2663.8,2014.38 2674.67,2003.5 2857.74,2003.5 2877.82,1983.43 2947.99,1983.43 2964.41,1999.84 2964.41,2087.44 3010.83,2133.86 R27.2@3055.12,2133.86 ; v1@2059,1940.94 cw(c2077.88,1940.94) 2064.53,1954.29 ; 3019.67,2133.86 cw(c3019.67,2098.41) 3044.73,2123.47 ccw(c3019.67,2098.41) 3019.67,2133.86 ; 3019.67,2133.86 ccw(c3019.67,2169.31) 3044.73,2144.24 cw(c3019.67,2169.31) 3019.67,2133.86
  other v1: 2051,1940.94
PA4: R59.1 U1.29 U10.1 | length 1596.7
  Top Layer w10: R59.1@2078.74,2531.5 2118.11,2531.5 2126.18,2539.57 U10.1@2212.6,2539.57 ; R59.1@2089.12,2521.11 cw(c2114.19,2496.04) 2114.19,2531.5 cw(c2114.19,2566.95) R59.1@2089.12,2541.88 ; U10.1@2153.24,2533.36 ccw(c2138.25,2518.37) 2138.25,2539.57 ccw(c2138.25,2560.76) U10.1@2153.24,2545.77
  Bottom Layer w8: U1.29@2053.15,2031.5 2242.91,2031.5 2268.18,2006.23 2290.45,2006.23 2318.9,2034.68 2318.9,2120.87 2401.18,2203.15 2401.18,2238.98 2368.11,2272.05 2247.47,2272.05 2229.92,2254.5 2229.92,2188.58 2209.46,2168.12 2187.11,2168.12 2156.69,2198.53 2156.69,2279.6 2212.08,2334.99 2212.08,2359.81 2189.61,2382.28 2170.79,2382.28 2078.74,2474.34 v1(2078.74,2566.93) ; v1@2072.38,2560.57 cw(c2057.01,2545.2) 2078.74,2545.2 cw(c2100.47,2545.2) v1@2085.1,2560.57
PA5: U1.30
PA6: U1.31
PA7: R21.2 U1.32 | length 1535.2
  Top Layer w10: v1@2027.56,1893.42 2153.83,1893.42 2169.61,1877.64 2657.8,1877.64 2663.39,1872.05 v1(2923.23,1872.05) ; v1@2033.22,1888.04 cw(c2046.19,1875.07) 2046.19,1893.42 ; v1@2033.22,1899.36 ccw(c2047.56,1913.7) 2047.56,1893.42 ; v1@2917.57,1866.39 ccw(c2903.91,1852.73) 2903.91,1872.05 ccw(c2903.91,1891.36) v1@2917.57,1877.7
  Bottom Layer w8: v1@2021.2,1887.34 ccw(c2005.83,1871.97) 2005.83,1893.7 ccw(c2005.83,1915.43) v1@2021.2,1900.06 ; v1(2027.56,1893.7) 1933.07,1893.7 1917.32,1909.45 1917.32,2019.68 1988.19,2090.55 U1.32@2053.15,2090.55 ; v1@2923.23,1881.05 ccw(c2923.23,1902.78) 2938.59,1887.41 ccw(c2953.96,1872.05) v1@2932.23,1872.05 ; v1@2925.2,1874.02 R21.2@2960.63,1909.45 ; R21.2@2944.95,1909.45 cw(c2907.08,1909.45) 2933.85,1882.67 cw(c2960.63,1855.9) R21.2@2960.63,1893.76
PA8: R39.2 U1.67 | length 1806.9
  Top Layer w10: v1(2421.26,2606.3) 2554.72,2606.3 2578.74,2630.32 3003.54,2630.32 3090.83,2543.02 3090.83,2453.03 3070.87,2433.07 3070.87,2358.27 3176.34,2252.8 3176.34,2036.26 v1(3204.72,2007.87) ; v1@2426.92,2600.64 cw(c2440.57,2586.99) 2440.57,2606.3 cw(c2440.57,2625.61) v1@2426.92,2611.96 ; v1@3196.72,2007.87 ccw(c3177.41,2007.87) 3191.07,2021.53 ccw(c3204.72,2035.19) v1@3204.72,2015.87
  Bottom Layer w10: v1@2415.6,2600.64 cw(c2382.94,2567.98) 2429.13,2567.98 ; v1@2422.67,2607.71 cw(c2407.08,2592.12) 2429.13,2592.12 ; U1.67@2429.13,2505.91 v1@2429.13,2607.87 ; v1@3204.72,1999.87 cw(c3204.72,1980.56) 3218.38,1994.22 cw(c3232.04,2007.87) v1@3212.72,2007.87 ; v1(3204.72,2007.87) 3248.03,1964.57 3326.77,1964.57 R39.2@3362.2,2000 ; R39.2@3347.52,2000 cw(c3312.07,2000) 3337.14,1974.93 cw(c3362.2,1949.86) R39.2@3362.2,1985.32
PA9: J1.7 U1.68 | length 1385.8
  Top Layer w10: J1.7@1759.84,2109.45 1811.81,2161.42 1927.17,2161.42 1972.13,2116.46 2226.52,2116.46 2237.86,2127.8 v1@2449.63,2127.8 ; J1.7@1759.84,2123.98 ccw(c1759.84,2159.05) 1784.64,2134.25 ccw(c1809.44,2109.45) J1.7@1774.37,2109.45 ; J1.7@1759.84,2133.98 ccw(c1759.84,2193.19) 1801.71,2151.32 ccw(c1843.58,2109.45) J1.7@1784.37,2109.45 ; 2410.21,2127.8 ccw(c2410.21,2174.4) v1@2443.16,2141.44 ; 2434.35,2127.8 ccw(c2434.35,2150.25) v1@2450.23,2134.37
  Bottom Layer w8: v1@2442.13,2141.81 2472.83,2172.52 2472.83,2327.99 2448.82,2352 U1.68@2448.82,2505.91 ; v1@2449.82,2135.84 cw(c2478.67,2137.49) 2458.24,2157.92 ; v1@2457.8,2136.3 cw(c2502.57,2138.84) 2470.86,2170.55
  other v1: 2448.82,2135.79
PA10: J1.9 U1.69 | length 1464
  Top Layer w10: J1.9@1759.84,2009.45 1809.45,2059.06 1872.98,2059.06 1888.06,2043.98 2096.62,2043.98 2129.42,2076.77 2244.29,2076.77 2255.08,2087.56 2377.02,2087.56 2377.52,2087.05 2383.27,2087.05 2405.36,2064.96 2462.6,2064.96 2484.65,2087.01 v1@2484.65,2139.76 ; J1.9@1759.84,2023.98 ccw(c1759.84,2059.05) 1784.64,2034.25 ccw(c1809.44,2009.45) J1.9@1774.37,2009.45 ; J1.9@1759.84,2033.98 ccw(c1759.84,2093.19) 1801.71,2051.32 ccw(c1843.58,2009.45) J1.9@1784.37,2009.45 ; v1@2479.03,2134.23 cw(c2465.47,2120.66) 2484.65,2120.66 ; 2484.65,2120.47 cw(c2504.09,2120.47) v1@2490.34,2134.23
  Bottom Layer w8: U1.69@2468.5,2505.91 2468.5,2357.55 2493.7,2332.36 v1@2493.7,2138.98 ; v1@2478.32,2146.25 ccw(c2441.19,2183.38) 2493.7,2183.38 ; v1@2483.98,2140.59 ccw(c2460.5,2164.06) 2493.7,2164.06
  other v1: 2484.68,2139.88
PA11: U1.70
PA12: U1.71
PA13: J1.8 R48.2 U1.72 | length 1948
  Top Layer w10: J1.8@1859.84,2084.92 cw(c1859.84,2027.61) 1900.37,2068.13 ; J1.8@1859.84,2094.92 cw(c1859.84,2061.75) 1883.3,2085.21 ; J1.8@1859.84,2108.66 1904.69,2063.82 2088.4,2063.82 2121.2,2096.61 2234.74,2096.61 2245.52,2107.4 2423.11,2107.4 v1@2423.23,2107.28 ; J1.8@1874.37,2109.45 ccw(c1911.34,2109.45) 1885.2,2083.3 ; J1.8@1884.37,2109.45 ccw(c1945.49,2109.45) 1902.27,2066.23 ; 2383.72,2107.28 cw(c2383.72,2061.09) v1@2416.39,2093.75 ; 2407.87,2107.28 cw(c2407.87,2085.23) v1@2423.46,2100.82
  Bottom Layer w8: v1@2420.87,2108.27 2491.66,2108.27 2511.54,2128.15 2511.54,2351.65 2501.57,2361.61 2501.57,2439.77 2527.56,2465.75 U1.72@2527.56,2505.91 ; v1@2422.75,2098.7 cw(c2445.85,2075.61) 2445.85,2108.27 ; v1@2428.41,2093.05 cw(c2465.16,2056.3) 2465.16,2108.27
  Bottom Layer w10: R48.2@1637.8,1862.2 1700.79,1925.2 1700.79,2027.56 1732.28,2059.06 1809.45,2059.06 J1.8@1859.84,2109.45 ; R48.2@1637.8,1876.89 ccw(c1637.8,1912.34) 1662.86,1887.27 ccw(c1687.93,1862.2) R48.2@1652.48,1862.2 ; J1.8@1835.32,2109.45 cw(c1776.1,2109.45) 1817.97,2067.58 cw(c1859.84,2025.71) J1.8@1859.84,2084.92 ; J1.8@1845.32,2109.45 cw(c1810.24,2109.45) 1835.04,2084.65 cw(c1859.84,2059.85) J1.8@1859.84,2094.92
  other v1: 2422.05,2099.41
PA14: J1.6 R49.2 U1.76 | length 1854.5
  Top Layer w10: J1.6@1859.84,2209.45 1908.66,2209.45 ; J1.6@1879.52,2194.81 cw(c1908.66,2173.13) 1908.66,2209.45 ; J1.6@1879.52,2224.09 ccw(c1908.66,2245.76) 1908.66,2209.45 ; 2500.06,2171.26 cw(c2500.06,2125.06) v1@2532.73,2157.73 ; 2524.2,2171.26 cw(c2524.2,2149.2) v1@2539.8,2164.8 ; v1@2539.37,2171.26 2423.23,2171.26 2399.99,2148.03 2230.03,2148.03 2219.79,2137.8 1980.31,2137.8 1908.66,2209.45
  Bottom Layer w8: v1@2529.53,2162.4 2529.53,2364.91 2519.42,2375.02 2519.42,2432.38 2535.14,2448.1 ; 2529.53,2187.19 ccw(c2562.19,2187.19) v1@2539.09,2164.09 ; 2529.53,2206.5 ccw(c2581.5,2206.5) v1@2544.75,2169.75 ; 2534.17,2447.13 2535.14,2448.1 ; U1.76@2647.64,2444.88 2560.6,2444.88 2557.38,2448.1 2535.14,2448.1
  Bottom Layer w10: R49.2@1637.97,2247.85 cw(c1664.54,2221.28) 1664.54,2258.86 ; R49.2@1641.73,2258.86 1810.43,2258.86 J1.6@1859.84,2209.45 ; R49.2@1645.05,2240.78 cw(c1688.69,2197.14) 1688.69,2258.86 ; R49.2@1652.12,2233.71 cw(c1712.83,2173) 1712.83,2258.86 ; J1.6@1835.32,2209.45 ccw(c1776.1,2209.45) 1817.97,2251.32 ccw(c1859.84,2293.19) J1.6@1859.84,2233.98 ; J1.6@1845.32,2209.45 ccw(c1810.24,2209.45) 1835.04,2234.25 ccw(c1859.84,2259.05) J1.6@1859.84,2223.98
  other v1: 2538.39,2163.39
PA15: U1.77
PB0: R14.2 U1.35 | length 932.2
  Top Layer w10: v1@2309.05,2216.54 2352.8,2260.28 2398.98,2260.28 2407.02,2252.24 2716.26,2252.24 2740.16,2228.35 R14.2@2792.32,2228.35 ; v1@2310.63,2226.11 ccw(c2310.63,2245.42) 2324.29,2231.77 ccw(c2337.94,2218.11) v1@2318.63,2218.11 ; R14.2@2780.95,2217.96 ccw(c2755.89,2192.89) 2755.89,2228.35 ccw(c2755.89,2263.8) R14.2@2780.95,2238.73
  Bottom Layer w8: U1.35@2053.15,2149.61 2155.16,2149.61 2172.33,2132.43 2224.56,2132.43 v1@2308.66,2216.54 ; 2294.59,2202.47 cw(c2310.63,2186.43) v1@2310.63,2209.11 ; 2295.54,2203.42 ccw(c2280.85,2218.11) v1@2301.63,2218.11
  other v1: 2310.63,2218.11
PB1: R16.2 U1.36 | length 966.3
  Top Layer w10: v1(2257.09,2243.7) 2313.35,2299.97 2415.42,2299.97 2423.46,2291.93 2714.19,2291.93 2721.48,2299.21 R16.2@2791.34,2299.21 ; v1@2257.09,2251.7 ccw(c2257.09,2271.01) 2270.74,2257.36 ccw(c2284.4,2243.7) v1@2265.09,2243.7 ; R16.2@2780.95,2288.83 ccw(c2755.89,2263.76) 2755.89,2299.21 ccw(c2755.89,2334.67) R16.2@2780.95,2309.6
  Bottom Layer w8: U1.36@2053.15,2169.29 2160.7,2169.29 2179.72,2150.28 2216.85,2150.28 2257.48,2190.91 v1@2257.48,2244.09 ; v1@2250.72,2237.34 cw(c2234.41,2221.02) 2257.48,2221.02 ; 2257.48,2222.92 cw(c2277.86,2222.92) v1@2263.45,2237.34
PB2: R44.2 U1.37 | length 150
  Bottom Layer w8: R44.2@1960.63,2188.98 U1.37@2051.18,2188.98 ; R44.2@1971.72,2177.89 cw(c1998.5,2151.11) 1998.5,2188.98 cw(c1998.5,2226.84) R44.2@1971.72,2200.07
PB3: R58.1 U1.89 U10.6 | length 593.6
  Top Layer w10: U10.6@2448.82,2439.57 R58.1@2577.36,2439.57 ; U10.6@2508.18,2433.36 cw(c2523.16,2418.37) 2523.16,2439.57 cw(c2523.16,2460.76) U10.6@2508.18,2445.77 ; 2539.96,2439.57 ccw(c2539.96,2479.72) R58.1@2568.36,2451.33 ; 2546.61,2439.57 cw(c2546.61,2408.82) R58.1@2568.36,2430.56
  Bottom Layer w8: v1@2539.9,2414.9 cw(c2503.14,2378.14) 2555.12,2378.14 ; v1@2545.55,2420.55 cw(c2522.46,2397.46) 2555.12,2397.46 ; v1@2555.12,2422.24 2555.12,2216.54 2582.68,2188.98 U1.89@2647.64,2188.98
  other v1: 2546.26,2421.26
PB4: R56.1 U1.90 U10.2 | length 1221.8
  Top Layer w10: R56.1@2078.74,2460.63 2107.68,2489.57 U10.2@2212.6,2489.57 2315.55,2489.57 2332.68,2472.44 v1@2332.68,2440.94 ; R56.1@2078.74,2475.31 ccw(c2078.74,2510.77) 2103.81,2485.7 ccw(c2128.88,2460.63) R56.1@2093.43,2460.63 ; U10.2@2153.24,2483.36 ccw(c2138.25,2468.37) 2138.25,2489.57 ccw(c2138.25,2510.76) U10.2@2153.24,2495.77 ; U10.2@2271.96,2483.36 cw(c2286.94,2468.37) 2286.94,2489.57 cw(c2286.94,2510.76) U10.2@2271.96,2495.77 ; v1@2327.02,2448.57 ccw(c2313.36,2462.23) 2332.68,2462.23 ccw(c2351.99,2462.23) v1@2338.33,2448.57
  Bottom Layer w8: v1@2332.68,2433.91 cw(c2332.68,2412.19) 2348.04,2427.55 cw(c2363.41,2442.91) v1@2341.68,2442.91 ; v1@2333.17,2442.42 2454.98,2320.61 2454.98,2181.19 2395.21,2121.42 2395.21,2084.72 2407.48,2072.44 2447.53,2072.44 2464.33,2089.24 2502.63,2089.24 2582.68,2169.29 U1.90@2647.64,2169.29
  other v1: 2332.68,2442.91
PB5: R57.1 U1.91 U10.5 | length 1122.6
  Top Layer w10: v1(2342.52,2389.76) 2555.12,2389.76 ; v1@2348.18,2384.11 cw(c2361.83,2370.45) 2361.83,2389.76 cw(c2361.83,2409.08) v1@2348.18,2395.42 ; 2374,2389.76 cw(c2374,2367.9) U10.5@2389.46,2383.36 ; 2374.95,2389.76 ccw(c2374.95,2410.29) U10.5@2389.46,2395.77 ; U10.5@2508.18,2383.36 cw(c2523.64,2367.9) 2523.64,2389.76 ; U10.5@2508.18,2395.77 ccw(c2522.69,2410.29) 2522.69,2389.76 ; R57.1@2564.07,2366.77 ccw(c2533.45,2368.09) 2555.12,2389.76 ; R57.1@2578.11,2380.81 cw(c2576.79,2411.44) 2555.12,2389.76 ; R57.1@2578.74,2366.14 2555.12,2389.76
  Bottom Layer w8: v1@2342.52,2380.76 cw(c2342.52,2359.04) 2357.88,2374.4 cw(c2373.25,2389.76) v1@2351.52,2389.76 ; v1@2343.01,2389.27 2437.13,2295.15 2437.13,2188.64 2377.29,2128.79 2377.29,2077.4 2400.09,2054.6 2457.06,2054.6 2473.79,2071.33 2520.15,2071.33 2598.43,2149.61 U1.91@2647.64,2149.61
PB6: U1.92
PB7: U1.93
PB8: R11.2 U1.95 | length 124.3
  Bottom Layer w8: v1@2568.01,2045.37 2593.5,2070.87 U1.95@2647.64,2070.87 ; v1@2568.11,2054.47 ccw(c2568.11,2076.2) 2583.47,2060.84 ccw(c2598.84,2045.47) v1@2577.11,2045.47
  other v1: 2568.11,2045.47
PB9: U1.96
PB10: R17.2 U1.47 | length 896.9
  Top Layer w10: v1@2185.43,2346.81 2424.7,2346.81 2439.9,2331.61 2604.57,2331.61 2604.61,2331.65 2615.86,2331.65 2615.9,2331.61 2697.76,2331.61 2736.22,2370.08 R17.2@2791.34,2370.08 ; v1@2190.89,2340.8 cw(c2205.41,2326.29) 2205.41,2346.81 ; v1@2190.89,2352.11 ccw(c2203.69,2364.92) 2203.69,2346.81 ; R17.2@2780.95,2359.7 ccw(c2755.89,2334.63) 2755.89,2370.08 ccw(c2755.89,2405.53) R17.2@2780.95,2380.46
  Bottom Layer w8: U1.47@2053.15,2385.83 2110.24,2385.83 2149.61,2346.46 v1@2185.43,2346.46 ; v1@2178.87,2340.09 ccw(c2163.51,2324.73) 2163.51,2346.46 ccw(c2163.51,2368.18) v1@2178.87,2352.82
  other v1: 2185.24,2346.46
PB11: R7.2 U1.48 | length 430.6
  Top Layer w10: v1@1958.91,2266 cw(c1945.25,2252.34) 1964.57,2252.34 cw(c1983.88,2252.34) v1@1970.22,2266 ; v1(1964.57,2271.65) 1964.57,2228.35 R7.2@2015.75,2177.17 ; R7.2@2001.06,2177.17 ccw(c1965.61,2177.17) 1990.68,2202.23 ccw(c2015.75,2227.3) R7.2@2015.75,2191.85
  Bottom Layer w8: v1(1964.57,2271.65) 2000,2307.09 2000,2393.7 2011.81,2405.51 U1.48@2053.15,2405.51 ; v1@1964.57,2280.65 ccw(c1964.57,2302.38) 1979.93,2287.02 ccw(c1995.29,2271.65) v1@1973.57,2271.65
PB12: R8.2 U1.51 | length 730.8
  Top Layer w10: R8.2@2015.75,2233.35 cw(c2015.75,2197.89) 2040.82,2222.96 cw(c2065.89,2248.03) R8.2@2030.43,2248.03 ; R8.2@2015.75,2248.03 2051.18,2212.6 2139.02,2212.6 2156.73,2194.88 v1@2198.03,2194.88 ; 2178.72,2194.88 ccw(c2178.72,2214.46) v1@2192.57,2200.62 ; 2179.1,2194.88 cw(c2179.1,2175.84) v1@2192.57,2189.3
  Bottom Layer w8: U1.51@2114.17,2505.91 2114.17,2464.14 2178.18,2400.13 2202.94,2400.13 2229.92,2373.15 2229.92,2327.6 2174.54,2272.21 2174.54,2218.77 v1@2198.43,2194.88 ; 2182.78,2210.53 cw(c2167.22,2194.96) v1@2189.23,2194.96 ; 2183.07,2210.24 ccw(c2198.23,2225.4) v1@2198.23,2203.96
  other v1: 2198.23,2194.96
PB13: R9.2 U1.52 | length 690.5
  Top Layer w10: R9.2@2015.75,2304.21 cw(c2015.75,2268.76) 2040.82,2293.83 cw(c2065.89,2318.9) R9.2@2030.43,2318.9 ; R9.2@2015.75,2318.9 2051.18,2283.46 2124.27,2283.46 2156.95,2250.79 v1@2200.79,2250.79 ; v1@2195.72,2245.13 ccw(c2182.06,2231.47) 2182.06,2250.79 ccw(c2182.06,2270.1) v1@2195.72,2256.44
  Bottom Layer w8: U1.52@2133.86,2505.91 2133.86,2469.69 2185.57,2417.97 2218.65,2417.97 2247.76,2388.85 2247.76,2320.2 2201.57,2274.02 v1@2201.57,2250.79 ; U1.52@2135.76,2476.38 ccw(c2156.52,2476.38) 2141.84,2461.7 ; v1@2195.01,2257.15 ccw(c2179.17,2272.99) 2201.57,2272.99 ; 2201.57,2272.04 ccw(c2222.63,2272.04) v1@2207.74,2257.15
  other v1: 2201.38,2250.79
PB14: U1.53 | length 178
  Bottom Layer w8: v2@2085.04,2597.3 cw(c2085.04,2568.09) 2105.69,2588.75 ; v2@2086.39,2608.04 2153.54,2540.89 U1.53@2153.54,2505.91 ; v2@2094.04,2606.3 ccw(c2108.29,2606.3) 2098.21,2596.22 ; 2146.43,2548.01 cw(c2133.86,2535.43) U1.53@2151.64,2535.43
  other v2: 2085.04,2606.3
PB15: U1.54
PC0: U1.15
PC1: R30.2 U1.16 | length 575.9
  Top Layer w10: v1@2493.95,2050.15 ccw(c2480.29,2063.8) 2499.61,2063.8 ccw(c2518.92,2063.8) v1@2505.26,2050.15 ; v1(2499.61,2044.49) 2499.61,2066.54 R30.2@2580.22,2147.15 ; R30.2@2567.99,2149.61 cw(c2532.54,2149.61) 2557.61,2124.54 cw(c2582.68,2099.47) R30.2@2582.68,2134.92
  Bottom Layer w8: U1.16@2291.34,1911.42 2291.34,1956.3 2370.51,2035.47 v1@2500.2,2035.47 ; 2456.11,2035.47 ccw(c2456.11,2087.98) v1@2493.24,2050.85 ; 2475.43,2035.47 ccw(c2475.43,2068.67) v1@2498.9,2045.2
PC2: R10.2 U1.17 | length 986
  Top Layer w10: R10.2@2015.75,2375.08 cw(c2015.75,2339.63) 2040.82,2364.69 cw(c2065.89,2389.76) R10.2@2030.43,2389.76 ; R10.2@2015.75,2389.76 2051.18,2354.33 2109.73,2354.33 2165.29,2298.77 v1@2264.57,2298.77 ; 2245.15,2298.77 ccw(c2245.15,2318.51) v1@2259.11,2304.55 ; 2245.75,2298.77 cw(c2245.75,2279.89) v1@2259.11,2293.24
  Bottom Layer w8: v1@2264.57,2298.82 2378.35,2298.82 2419.29,2257.87 2419.29,2196.03 2359.45,2136.18 2359.45,2049.64 2271.65,1961.85 U1.17@2271.65,1911.42 ; v1@2271.13,2292.53 cw(c2286.3,2277.36) 2286.3,2298.82 ; v1@2271.13,2305.26 ccw(c2286.68,2320.81) 2286.68,2298.82
  other v1: 2264.76,2298.9
PC3: R6.2 U1.18 | length 1134.8
  Top Layer w10: v1@2210.09,1983.32 cw(c2196.43,1969.66) 2215.75,1969.66 cw(c2235.06,1969.66) v1@2221.4,1983.32 ; v1(2215.75,1988.98) 2215.75,1957.48 2236.06,1937.17 2583.82,1937.17 2584.65,1937.99 2621.35,1974.69 2647.36,1974.69 2658.23,1963.82 2841.3,1963.82 2862.2,1942.91 2963.6,1942.91 2997.07,1976.38 R6.2@3055.12,1976.38 ; R6.2@3044.73,1965.99 ccw(c3019.67,1940.92) 3019.67,1976.38 ccw(c3019.67,2011.83) R6.2@3044.73,1986.76
  Bottom Layer w8: v1@2215.55,1989.17 2251.97,1952.76 U1.18@2251.97,1911.42 ; v1@2215.75,1979.98 cw(c2215.75,1958.25) 2231.11,1973.61 cw(c2246.48,1988.98) v1@2224.75,1988.98
PC4: R12.2 U1.33 | length 1004.1
  Top Layer w10: v1@2276.89,2040.67 2373.53,2040.67 2417.51,1996.69 2559.16,1996.69 2596.72,2034.25 2710.91,2034.25 2748.58,2071.93 ; v1@2277.92,2034.49 cw(c2292.85,2019.56) 2292.85,2040.67 ; v1@2284.99,2027.41 cw(c2316.99,1995.41) 2316.99,2040.67 ; 2763.14,2071.93 ccw(c2763.14,2097.45) R12.2@2786.97,2088.3 ; R12.2@2777.63,2091.88 cw(c2748.58,2103.05) 2748.58,2071.93 ; R12.2@2777.7,2071.93 ccw(c2777.7,2091.86) R12.2@2796.3,2084.71 ; R12.2@2795.28,2071.93 2748.58,2071.93
  Bottom Layer w8: U1.33@2053.15,2110.24 2144.06,2110.24 2157.55,2096.75 2215.46,2096.75 v1@2279.13,2033.07 ; 2263.63,2048.57 ccw(c2279.33,2064.27) v1@2279.33,2042.07 ; 2264.11,2048.1 cw(c2249.08,2033.07) v1@2270.33,2033.07
  other v1: 2279.33,2033.07
PC5: R13.2 U1.34 | length 927.5
  Top Layer w10: v1@2372.83,2212.44 2684.45,2212.44 2739.42,2157.48 R13.2@2791.34,2157.48 ; v1@2378.29,2206.94 cw(c2391.57,2193.66) 2391.57,2212.44 ; v1@2378.29,2218.26 ccw(c2392.33,2232.29) 2392.33,2212.44 ; R13.2@2780.95,2147.1 ccw(c2755.89,2122.03) 2755.89,2157.48 ccw(c2755.89,2192.93) R13.2@2780.95,2167.86
  Bottom Layer w8: U1.34@2053.15,2129.92 2149.61,2129.92 2164.94,2114.59 2274.83,2114.59 v1@2372.44,2212.2 ; 2357.13,2196.9 ccw(c2341.44,2212.6) v1@2363.64,2212.6 ; 2357.61,2197.37 cw(c2372.64,2182.35) v1@2372.64,2203.6
  other v1: 2372.64,2212.6
PC6: U1.63 U9.3 | length 738.3
  Top Layer w8: v2(2185.04,2606.3) 2245.74,2667 2487.08,2667 2497.24,2677.17 U9.3@2497.24,2734.65 ; v2@2185.04,2615.3 ccw(c2185.04,2637.03) 2200.4,2621.66 ccw(c2215.77,2606.3) v2@2194.04,2606.3 ; U9.3@2490.53,2695.84 cw(c2474.31,2679.62) 2497.24,2679.62 ; 2497.24,2678.67 cw(c2521.53,2678.67) U9.3@2504.36,2695.84
  Bottom Layer w8: v2@2185.04,2597.3 cw(c2185.04,2575.57) 2200.4,2590.93 cw(c2215.77,2606.3) v2@2194.04,2606.3 ; v2(2185.04,2606.3) 2212.2,2579.13 2323.16,2579.13 2350.39,2551.9 U1.63@2350.39,2505.91
PC7: R65.1 R68.2 U1.64 U12.6 | length 1342.2
  Top Layer w8: v2(2285.04,2606.3) 2312.6,2633.86 2555.12,2633.86 2570.42,2649.16 2731.83,2649.16 2748.03,2665.35 U12.6@2748.03,2732.28 ; v2@2285.04,2615.3 ccw(c2285.04,2637.03) 2300.4,2621.66 ccw(c2315.77,2606.3) v2@2294.04,2606.3 ; 2617.88,2649.16 ccw(c2617.88,2701.72) v1@2655.05,2664.55 ; 2637.2,2649.16 ccw(c2637.2,2682.41) v1@2660.71,2658.9 ; v1@2662.12,2658.9 ccw(c2685.64,2682.41) 2685.64,2649.16 ; v1@2667.78,2664.55 ccw(c2704.95,2701.72) 2704.95,2649.16 ; U12.6@2739.74,2695.84 cw(c2719.72,2675.82) 2748.03,2675.82 ; 2748.03,2682.47 cw(c2766.94,2682.47) U12.6@2753.57,2695.84
  Bottom Layer w8: v2@2283.46,2606.3 2321.22,2606.3 2370.08,2557.44 U1.64@2370.08,2505.91 ; v2@2291.4,2599.94 cw(c2306.77,2584.57) 2306.77,2606.3 cw(c2306.77,2628.03) v2@2291.4,2612.66 ; R68.2@2650.33,2733 cw(c2623.55,2706.23) 2661.42,2706.23 cw(c2699.28,2706.23) R68.2@2672.51,2733 ; v1@2655.05,2664.55 ccw(c2639.69,2679.92) 2661.42,2679.92 ccw(c2683.15,2679.92) v1@2667.78,2664.55 ; v1(2661.42,2658.19) R68.2@2661.42,2744.09
  Bottom Layer w10: R68.2@2661.42,2744.09 R65.1@2759.84,2744.09 ; R68.2@2671.8,2733.71 cw(c2696.87,2708.64) 2696.87,2744.09 cw(c2696.87,2779.55) R68.2@2671.8,2754.48 ; R65.1@2749.46,2733.71 ccw(c2724.39,2708.64) 2724.39,2744.09 ccw(c2724.39,2779.55) R65.1@2749.46,2754.48
PC8: R68.1 U1.65 | length 499
  Bottom Layer w8: U1.65@2389.76,2505.91 2389.76,2563.35 2387.92,2565.19 2387.56,2565.19 2357.09,2595.67 2357.09,2652.36 2448.82,2744.09 R68.1@2598.43,2744.09 ; R68.1@2587.33,2733 ccw(c2560.56,2706.23) 2560.56,2744.09 ccw(c2560.56,2781.96) R68.1@2587.33,2755.19
PC9: U1.66 U6.2 | length 621.1
  Top Layer w10: U6.2@2134.15,2696.55 cw(c2119.16,2681.56) 2140.35,2681.56 cw(c2161.55,2681.56) U6.2@2146.56,2696.55 ; U6.2@2140.35,2738.19 2140.35,2607.68 2169.57,2578.46 2357.2,2578.46 v2(2385.04,2606.3) ; v2@2377.04,2606.3 cw(c2357.73,2606.3) 2371.38,2592.64 cw(c2385.04,2578.99) v2@2385.04,2598.3
  Bottom Layer w8: v2@2378.35,2600.2 2409.45,2569.09 U1.66@2409.45,2507.87 ; v2@2386.02,2606.12 ccw(c2408.07,2602.15) 2392.23,2586.31 ; v2@2393.9,2604.7 ccw(c2426.41,2598.85) 2403.05,2575.49
PC10: R37.2 U1.78 | length 258.3
  Bottom Layer w8: U1.78@2647.64,2405.51 2694.88,2405.51 2712.05,2422.68 2712.05,2472.87 R37.2@2754.92,2515.75 ; 2727.45,2488.28 cw(c2755.91,2459.82) R37.2@2755.91,2500.06 ; 2729.83,2490.65 ccw(c2704.73,2515.75) R37.2@2740.22,2515.75 ; R37.2@2741.11,2501.93 cw(c2755.91,2487.13) R37.2@2755.91,2508.06
PC11: U1.79
PC12: U1.80
PC13: U1.7
PC14: C51.2 R45.2 U1.8 X1.2 | length 1394.9
  Bottom Layer w8: C51.2@1732.28,1586.61 R45.2@1933.07,1586.61 2001.91,1517.78 2411.48,1517.78 2442.67,1548.97 2442.67,1576.57 2452.76,1586.66 2452.76,1690.39 2431.04,1712.1 2431.04,1831 2448.82,1848.78 U1.8@2448.82,1911.42 ; C51.2@1743.37,1575.52 cw(c1770.15,1548.75) 1770.15,1586.61 cw(c1770.15,1624.48) C51.2@1743.37,1597.71 ; X1.2@1811.85,1579 ccw(c1793.48,1560.63) 1793.48,1586.61 ccw(c1793.48,1612.6) X1.2@1811.85,1594.23 ; X1.2@1856.6,1579 cw(c1874.98,1560.63) 1874.98,1586.61 cw(c1874.98,1612.6) X1.2@1856.6,1594.23 ; R45.2@1921.98,1575.52 ccw(c1895.2,1548.75) 1895.2,1586.61 ccw(c1895.2,1624.48) R45.2@1921.98,1597.71 ; R45.2@1933.07,1570.93 cw(c1933.07,1533.06) 1959.85,1559.84 cw(c1986.62,1586.61) R45.2@1948.76,1586.61
PC15: C52.2 R45.1 U1.9 X1.1 | length 1431.7
  Bottom Layer w8: C52.2@1732.28,1712.6 1870.08,1712.6 ; C52.2@1743.37,1701.51 cw(c1770.15,1674.73) 1770.15,1712.6 cw(c1770.15,1750.47) C52.2@1743.37,1723.69 ; X1.1@1811.85,1704.99 ccw(c1793.48,1686.61) 1793.48,1712.6 ccw(c1793.48,1738.58) X1.1@1811.85,1720.21 ; X1.1@1857.71,1706.28 cw(c1870.08,1697.32) 1870.08,1712.6 ; X1.1@1857.71,1718.91 ccw(c1870.08,1727.88) 1870.08,1712.6 ; R45.1@1917.39,1649.61 ccw(c1879.52,1649.61) 1906.3,1676.38 ccw(c1933.07,1703.16) R45.1@1933.07,1665.29 ; R45.1@1944.68,1639.06 cw(c1968.5,1617.43) 1968.5,1649.61 ; R45.1@1944.68,1660.15 ccw(c1968.5,1681.78) 1968.5,1649.61 ; U1.9@2429.13,1911.42 2429.13,1854.33 2413.2,1838.39 2413.2,1704.71 2434.91,1682.99 2434.91,1594.05 2424.83,1583.96 2424.83,1558.69 2401.76,1535.62 2011.62,1535.62 1980.32,1566.93 1980.32,1637.8 1968.5,1649.61 ; 1870.08,1712.6 R45.1@1933.07,1649.61 1968.5,1649.61
PD0: U1.81
PD1: U1.82
PD2: U1.83
PD3: U1.84
PD4: U1.85
PD5: U1.86
PD6: U1.87
PD7: U1.88
PD8: R50.1 U1.55 | length 386.2
  Bottom Layer w8: R50.1@1968.5,2578.74 2011.81,2578.74 2066.21,2633.14 2101.47,2633.14 2133.86,2600.75 2133.86,2594.29 2166.53,2561.61 2166.73,2561.61 2167.08,2561.26 2177.24,2561.26 2192.91,2545.59 U1.55@2192.91,2505.91 ; R50.1@1979.59,2567.65 cw(c2006.37,2540.87) 2006.37,2578.74 cw(c2006.37,2616.61) R50.1@1979.59,2589.83
PD9: R51.1 U1.56 | length 543.8
  Bottom Layer w8: R51.1@1962.62,2655.49 cw(c1986.45,2631.66) R51.1@1986.45,2665.35 ; R51.1@1968.28,2649.83 cw(c2005.76,2612.35) 2005.76,2665.35 ; R51.1@1968.5,2649.61 1984.25,2665.35 2094.49,2665.35 2156.65,2603.2 2156.65,2596.93 2158.2,2595.38 2158.2,2595.18 2173.92,2579.46 2174.12,2579.46 2174.47,2579.11 2184.63,2579.11 2212.6,2551.14 U1.56@2212.6,2505.91 ; R51.1@1973.94,2644.17 cw(c2025.08,2593.03) 2025.08,2665.35 ; R51.1@1979.59,2638.52 cw(c2044.39,2573.72) 2044.39,2665.35
PD10: U1.57
PD11: U1.58
PD12: U1.59
PD13: U1.60
PD14: U1.61
PD15: U1.62
PE0: U1.97
PE1: U1.98
PE2: U1.1
PE3: U1.2
PE4: U1.3
PE5: U1.4
PE6: U1.5
PE7: U1.38
PE8: U1.39
PE9: U1.40
PE10: U1.41
PE11: U1.42
PE12: U1.43
PE13: U1.44
PE14: U1.45
PE15: U1.46
RE#: R62.1 U11.2 | length 290.3
  Bottom Layer w10: 2273.74,2983.15 ccw(c2288.12,2997.53) U11.2@2294.49,2978.22 ; R62.1@2308.15,3106.3 cw(c2272.7,3106.3) 2297.77,3081.23 cw(c2322.83,3056.16) R62.1@2322.83,3091.61 ; R62.1@2322.83,3106.3 2268.62,3052.09 2268.62,2988.27 2287.01,2969.88 U11.2@2332.68,2969.88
